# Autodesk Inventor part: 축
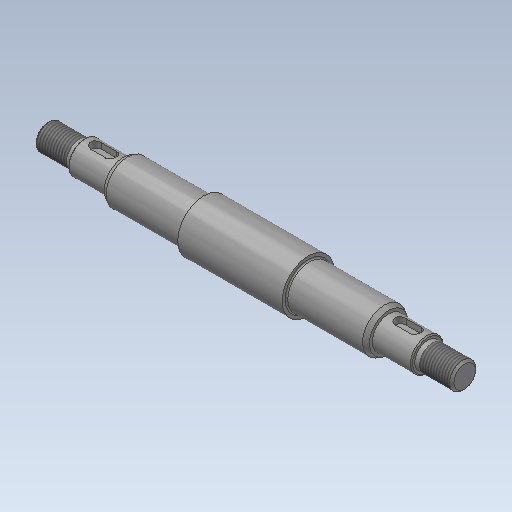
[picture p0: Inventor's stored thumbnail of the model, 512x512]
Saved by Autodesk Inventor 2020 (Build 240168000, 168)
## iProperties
Created: 2018-11
Part Number: 축
Material: 강철, 연강
Document SubType Name: Modeling
Designer: mduedu
Density: 1 g/cm^3
Appearance: 강철
Author: mduedu
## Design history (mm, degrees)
sketch "스케치1"
  geometry: L1 (-24, 0)-(24, 0); L2 (24, 0)-(24, 12); L3 (24, 12)-(-24, 12); L4 (-24, 12)-(-24, 0); L5 (-24, 0)-(-79, 0); L6 (-79, 0)-(-79, 7.5); L7 (-79, 7.5)-(-61, 7.5); L8 (-24, 7.5)-(-24, 0); L9 (-79, 0)-(-96, 0); L10 (-96, 0)-(-96, 6); L11 (-96, 6)-(-79, 6); L12 (-79, 6)-(-79, 0); L13 (0, 0)-(0, 12); L14 (24, 0)-(79, 0); L15 (79, 0)-(79, 7.5); L16 (79, 7.5)-(61, 7.5); L17 (24, 7.5)-(24, 0); L18 (79, 0)-(96, 0); L19 (96, 0)-(96, 6); L20 (96, 6)-(79, 6); L21 (79, 6)-(79, 0); L22 (-61, 7.5)-(-61, 8.85); L23 (-59.008, 10)-(-24, 10); L24 (24, 10)-(59.008, 10); L25 (61, 8.85)-(61, 7.5); L26 (-61, 8.85)-(-59.008, 10); L27 (61, 8.85)-(59.008, 10); 1 further point
  constraints: 54 end point, 9 parallel, 6 symmetric about line, 4 horizontal, 4 perpendicular, 2 midpoint, 2 point on line, 1 coincident
  dimensions: "d0" = 24 diameter of L3 L1; "d2" = 15 diameter of L7 L5; "d3" = 12 diameter of L11 L9; "d4" = 48 distance of L2.end L3.end; "d5" = 55 distance of L6.end L8.start; "d6" = 192 distance between parallel lines of L19 L10; "d24" = 20 diameter of L23 L5; "d25" = 18 distance of L6.end L7.end; "d26" = 18 distance of L15.end L16.end; "d27" = 20 diameter of L24 L14; "d28" = 55 distance between parallel lines of L15 L2; "d29" = 30 deg angle of L23 L26; "d30" = 17.7 diameter of L22.end L5; "d31" = 30 deg angle of L24 L27; "d32" = 17.7 diameter of L25.start L14
revolve "회전1" sketch "스케치1" stored, may be unused: angle "d7" = 90 deg
fillet "모깎기1" dims "d8" = 0.6
node "작업 평면1"
sketch "스케치2" dims "d11" = 12
  geometry: L1 (-3.5, 2.5)-(3.5, 2.5); L2 (3.5, 2.5)-(3.5, -2.5); L3 (3.5, -2.5)-(-3.5, -2.5); L4 (-3.5, -2.5)-(-3.5, 2.5); L5 (9, 7.5)-(9, -7.5) reference; 3 further points
  constraints: 8 end point, 2 midpoint, 2 parallel, 2 vertical alignment, 1 horizontal, 1 horizontal alignment, 1 perpendicular, 4 other
  dimensions: "d9" = 3 dimension on L5; "d10" = 5 distance between parallel lines of L3 L1
extrude "돌출1" cut sketch "스케치2" distance "d12" = 3; taper "d13" = 0 deg
chamfer "모따기1" distance "d14" = 0.5; stored, may be unused: second distance "d15" = 2, angle "d16" = 45 deg
feature "스레드1" dims "d17" = 15, "d18" = 0
feature "스레드2" dims "d19" = 15, "d20" = 0
chamfer "모따기2" distance "d21" = 1; stored, may be unused: second distance "d22" = 2, angle "d23" = 45 deg
node "솔리드1"
mirror "대칭1"
